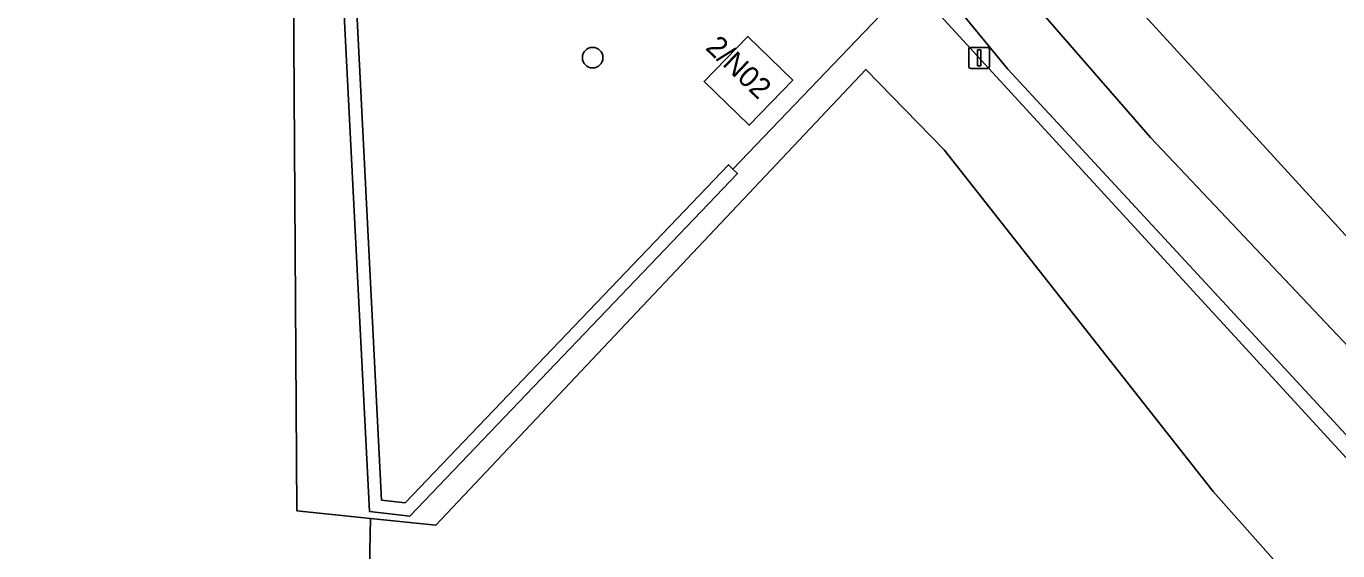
# Model space of a CAD drawing. Extents: x 160203 to 161530, y 379528 to 381797.
# Drawn here: x 160994.1 to 161056.6, y 381200.5 to 381225.4 of the extents above; entities that cross this region are included whole.
import ezdxf

# ---------------------------------------------------------------- set-up
doc = ezdxf.new("R2010")
doc.units = 0
for name, color, linetype in [('IMGEO_Boom', 7, 'Continuous'), ('IMGEO_Bouwland', 7, 'Continuous'), ('IMGEO_Erf', 7, 'Continuous'), ('IMGEO_Grasland_overig', 7, 'Continuous'), ('IMGEO_Groenvoorziening', 7, 'Continuous'), ('IMGEO_Haag', 7, 'Continuous'), ('IMGEO_Hek', 7, 'Continuous'), ('IMGEO_Loofbos', 7, 'Continuous'), ('IMGEO_Pand', 7, 'Continuous'), ('IMGEO_Pand_nummerreeks', 7, 'Continuous'), ('IMGEO_Rijbaan_lokaal_gesloten', 7, 'Continuous'), ('IMGEO_Verkeersbordpaal', 7, 'Continuous')]:
    doc.layers.add(name, color=color, linetype=linetype)

msp = doc.modelspace()

# ---------------------------------------------------------------- linework, layer by layer
at = {"layer": 'IMGEO_Boom'}
msp.add_circle((161021.103, 381223.95), 0.489, dxfattribs=at)
at = {"layer": 'IMGEO_Bouwland'}
msp.add_lwpolyline([(161006.784, 381168.689), (161006.955, 381196.823), (161010.411, 381196.554), (161010.514, 381202.004), (161007.008, 381202.372), (161006.713, 381247.124), (161000, 381248.889), (160995.774, 381250), (160995.157, 381250.162), (160994.1, 381250.44), (160993.954, 381250), (160939.305, 381085.021), (160943.925, 381083.756), (160975.971, 381079.297), (160994.378, 381077.678), (160995.21, 381078.26), (161000, 381077.092), (161003.548, 381076.227), (161010.953, 381074.647), (161010.972, 381081.302), (161009.282, 381081.264), (161007.34, 381139.766)], close=True, dxfattribs=at)
at = {"layer": 'IMGEO_Erf'}
for points in [[(161036.267, 381227.494), (161034.943, 381228.573), (161032.692, 381230.87), (161028.679, 381234.184), (161026.738, 381235.726), (161024.528, 381237.381), (161022.676, 381238.69), (161016.014, 381243.993), (161008.358, 381248.475), (161008.298, 381246.716), (161007.833, 381233.298), (161009.7, 381229.266), (161011.042, 381202.875), (161012.159, 381202.744), (161027.575, 381218.848), (161027.792, 381218.641)], [(161028.504, 381224.959), (161030.645, 381222.879), (161028.562, 381220.734), (161026.417, 381222.818)]]:
    msp.add_lwpolyline(points, close=True, dxfattribs=at)
at = {"layer": 'IMGEO_Grasland_overig'}
msp.add_lwpolyline([(161060.216, 381211.973), (161041.491, 381232.447), (161036.736, 381238.047), (161035.763, 381237.208), (161035.453, 381234.099), (161037.654, 381231.685), (161047.699, 381220.155), (161057.71, 381209.573)], close=True, dxfattribs=at)
at = {"layer": 'IMGEO_Groenvoorziening'}
for points in [[(161062.517, 381200.044), (161040.903, 381223.397), (161036.849, 381228.347), (161032.145, 381232.938), (161027.05, 381237.09), (161023.448, 381239.603), (161015.8, 381244.93), (161009.875, 381248.512), (161007.017, 381250), (161000, 381252.893), (160999.363, 381253.014), (160998.719, 381253.077), (160998.071, 381253.083), (160997.425, 381253.031), (160996.786, 381252.921), (160996.16, 381252.755), (160995.551, 381252.533), (160995.199, 381252.368), (160994.964, 381252.258), (160994.405, 381251.932), (160993.876, 381251.557)], [(160939.305, 381085.021), (160993.954, 381250), (160994.1, 381250.44), (160995.157, 381250.162), (160995.774, 381250), (161000, 381248.889), (161006.713, 381247.124), (161007.701, 381246.818), (161007.764, 381248.657), (161008.064, 381248.647), (161008.358, 381248.475), (161016.014, 381243.993), (161022.676, 381238.69), (161024.528, 381237.381), (161026.738, 381235.726), (161028.679, 381234.184), (161032.692, 381230.87), (161034.943, 381228.573), (161036.267, 381227.494), (161059.702, 381201.99)], [(161069.952, 381230.624), (161053.998, 381249.187), (161050.077, 381249.546), (161036.736, 381238.047), (161041.491, 381232.447), (161060.216, 381211.973)]]:
    msp.add_lwpolyline(points, dxfattribs=at)
for points in [[(161027.792, 381218.641), (161027.575, 381218.848), (161012.159, 381202.744), (161011.042, 381202.875), (161009.7, 381229.266), (161007.833, 381233.298), (161008.298, 381246.716), (161008.358, 381248.475), (161008.064, 381248.647), (161007.764, 381248.657), (161007.701, 381246.818), (161007.698, 381246.736), (161007.229, 381233.176), (161009.107, 381229.12), (161010.468, 381202.339), (161012.385, 381202.114), (161028.008, 381218.433)], [(161082.58, 381175.752), (161077.672, 381178.299), (161070.576, 381182.79), (161061.577, 381191.025), (161050.681, 381203.282), (161037.868, 381219.565), (161034.126, 381223.392), (161013.621, 381201.677), (161010.514, 381202.004), (161010.411, 381196.554), (161013.52, 381196.312), (161034.781, 381187.905), (161053.717, 381180.263), (161083.684, 381168.57), (161084.609, 381170.365), (161086.045, 381169.747), (161087.551, 381174.026), (161086.166, 381174.408)]]:
    msp.add_lwpolyline(points, close=True, dxfattribs=at)
at = {"layer": 'IMGEO_Haag'}
msp.add_lwpolyline([(161008.358, 381248.475), (161008.064, 381248.647), (161007.764, 381248.657), (161007.701, 381246.818), (161007.698, 381246.736), (161007.229, 381233.176), (161009.107, 381229.12), (161010.468, 381202.339), (161012.385, 381202.114), (161028.008, 381218.433), (161027.792, 381218.641), (161027.575, 381218.848), (161012.159, 381202.744), (161011.042, 381202.875), (161009.7, 381229.266), (161007.833, 381233.298), (161008.298, 381246.716)], close=True, dxfattribs=at)
at = {"layer": 'IMGEO_Hek'}
msp.add_lwpolyline([(161036.267, 381227.494), (161059.702, 381201.99), (161062.8, 381198.618), (161073.827, 381188.007), (161074.485, 381187.273), (161075.831, 381185.995), (161077.303, 381184.864), (161078.885, 381183.893), (161080.56, 381183.093), (161082.31, 381182.472), (161085.055, 381181.736)], dxfattribs=at)
at = {"layer": 'IMGEO_Loofbos'}
msp.add_lwpolyline([(161059.702, 381201.99), (161036.267, 381227.494), (161027.792, 381218.641), (161028.008, 381218.433), (161012.385, 381202.114), (161010.468, 381202.339), (161009.107, 381229.12), (161007.229, 381233.176), (161007.698, 381246.736), (161007.701, 381246.818), (161006.713, 381247.124), (161007.008, 381202.372), (161010.514, 381202.004), (161013.621, 381201.677), (161034.126, 381223.392), (161037.868, 381219.565), (161050.681, 381203.282), (161061.577, 381191.025)], dxfattribs=at)
at = {"layer": 'IMGEO_Pand'}
msp.add_lwpolyline([(161028.562, 381220.734), (161030.645, 381222.879), (161028.504, 381224.959), (161026.417, 381222.818)], close=True, dxfattribs=at)
at = {"layer": 'IMGEO_Rijbaan_lokaal_gesloten'}
for points in [[(161047.699, 381220.155), (161037.654, 381231.685), (161035.453, 381234.099), (161031.365, 381237.996), (161029.512, 381239.55), (161026.29, 381242.043), (161022.904, 381244.308), (161013.194, 381250), (161008.561, 381252.716), (161000, 381256.922)], [(160993.876, 381251.557), (160994.405, 381251.932), (160994.964, 381252.258), (160995.199, 381252.368), (160995.551, 381252.533), (160996.16, 381252.755), (160996.786, 381252.921), (160997.425, 381253.031), (160998.071, 381253.083), (160998.719, 381253.077), (160999.363, 381253.014), (161000, 381252.893), (161007.017, 381250), (161009.875, 381248.512), (161015.8, 381244.93), (161023.448, 381239.603), (161027.05, 381237.09), (161032.145, 381232.938), (161036.849, 381228.347), (161040.903, 381223.397), (161062.517, 381200.044)], [(161057.71, 381209.573), (161047.699, 381220.155)]]:
    msp.add_lwpolyline(points, dxfattribs=at)
at = {"layer": 'IMGEO_Verkeersbordpaal'}
for p, q in [((161039.032, 381223.54), (161039.032, 381224.34)), ((161039.032, 381224.34), (161039.032, 381223.54)), ((161039.132, 381224.44), (161039.922, 381224.44)), ((161039.922, 381224.44), (161039.132, 381224.44)), ((161040.022, 381224.34), (161040.022, 381223.54)), ((161040.022, 381223.54), (161040.022, 381224.34)), ((161039.922, 381223.44), (161039.132, 381223.44)), ((161039.132, 381223.44), (161039.922, 381223.44))]:
    msp.add_line(p, q, dxfattribs=at)
msp.add_lwpolyline([(161039.452, 381224.315), (161039.602, 381224.315), (161039.602, 381223.565), (161039.452, 381223.565), (161039.452, 381224.315)], dxfattribs=at)
for centre, start, end in [((161039.132, 381224.34), 90, 180), ((161039.132, 381224.34), 90, 180), ((161039.922, 381224.34), 0, 90), ((161039.922, 381224.34), 360, 90), ((161039.132, 381223.54), 180, 270), ((161039.132, 381223.54), 180, 270), ((161039.922, 381223.54), 270, 0), ((161039.922, 381223.54), 270, 0)]:
    msp.add_arc(centre, 0.1, start, end, dxfattribs=at)

# ---------------------------------------------------------------- texts
at = {"layer": 'IMGEO_Pand_nummerreeks'}
msp.add_text('2/N02', height=1, rotation=316.32872, dxfattribs=at).set_placement((161026.441, 381224.375))

doc.saveas('drawing.dxf')
